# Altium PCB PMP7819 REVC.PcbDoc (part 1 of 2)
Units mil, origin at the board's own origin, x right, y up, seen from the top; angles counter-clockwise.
Board outline 2280 x 1450 mil, 4 copper layers (Top Layer, Mid-Layer 1, Mid-Layer 2, Bottom Layer), stack 62.2 mil thick; 94 components, 42 nets, 265 pads, 199 vias.
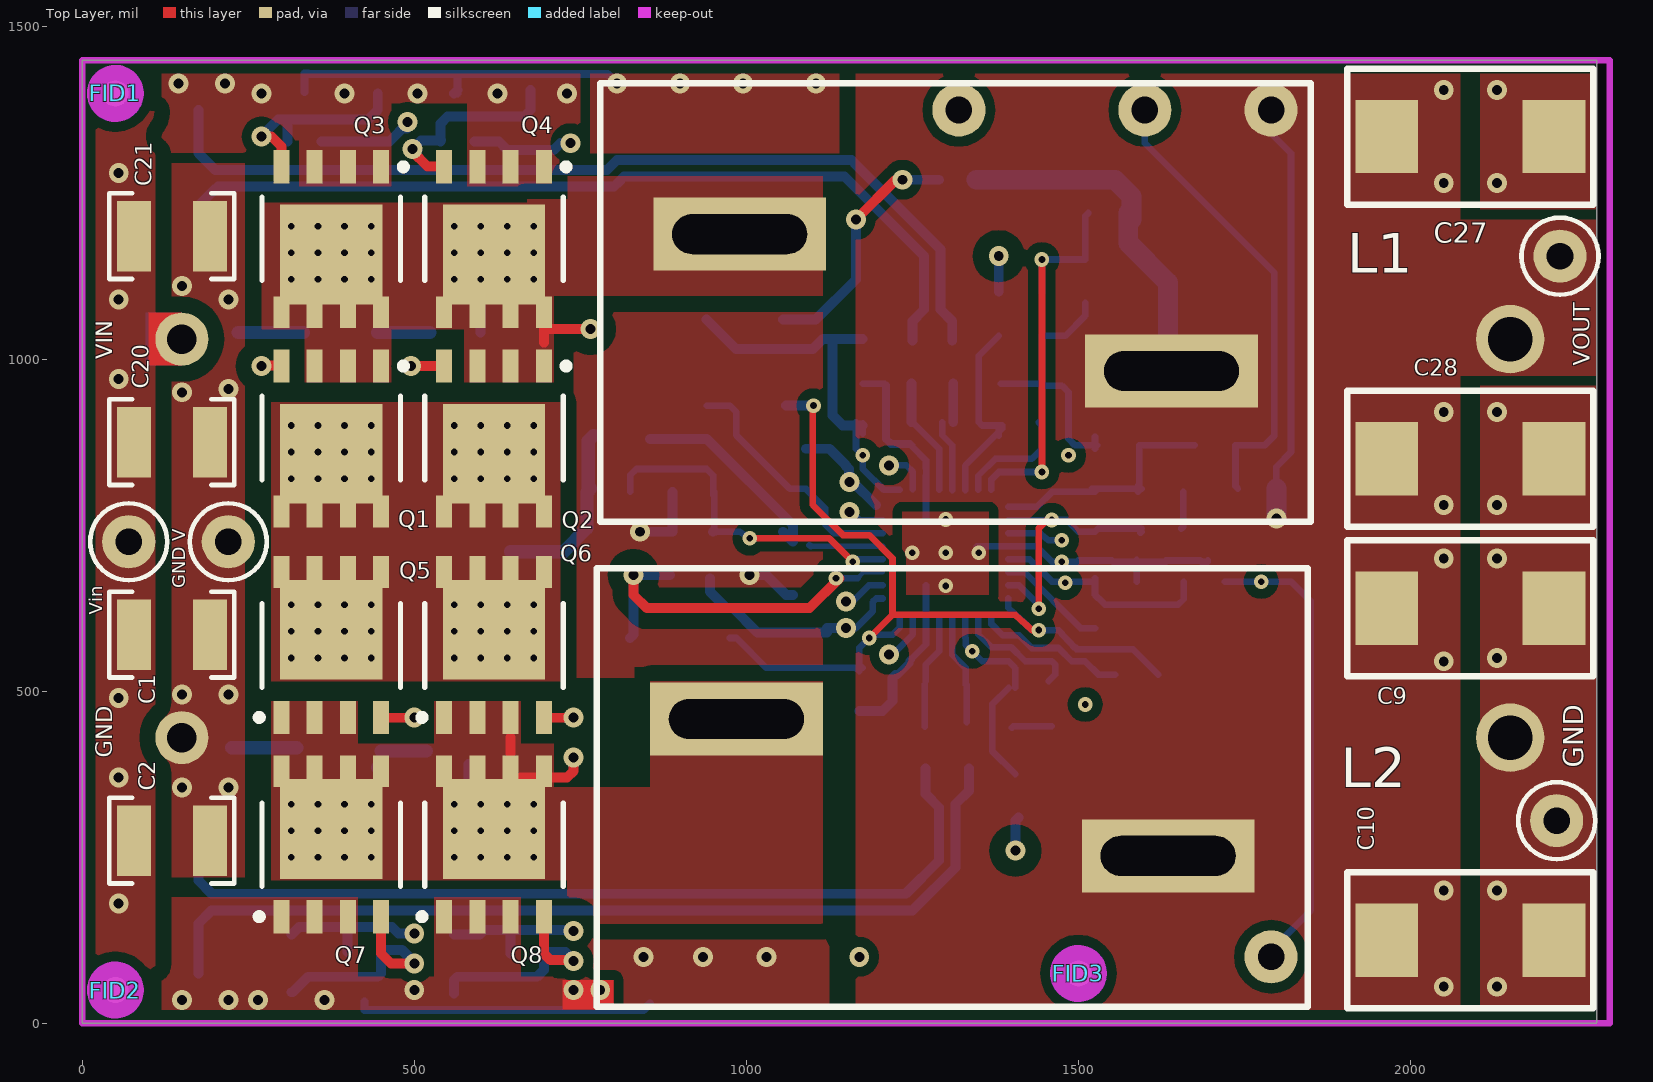
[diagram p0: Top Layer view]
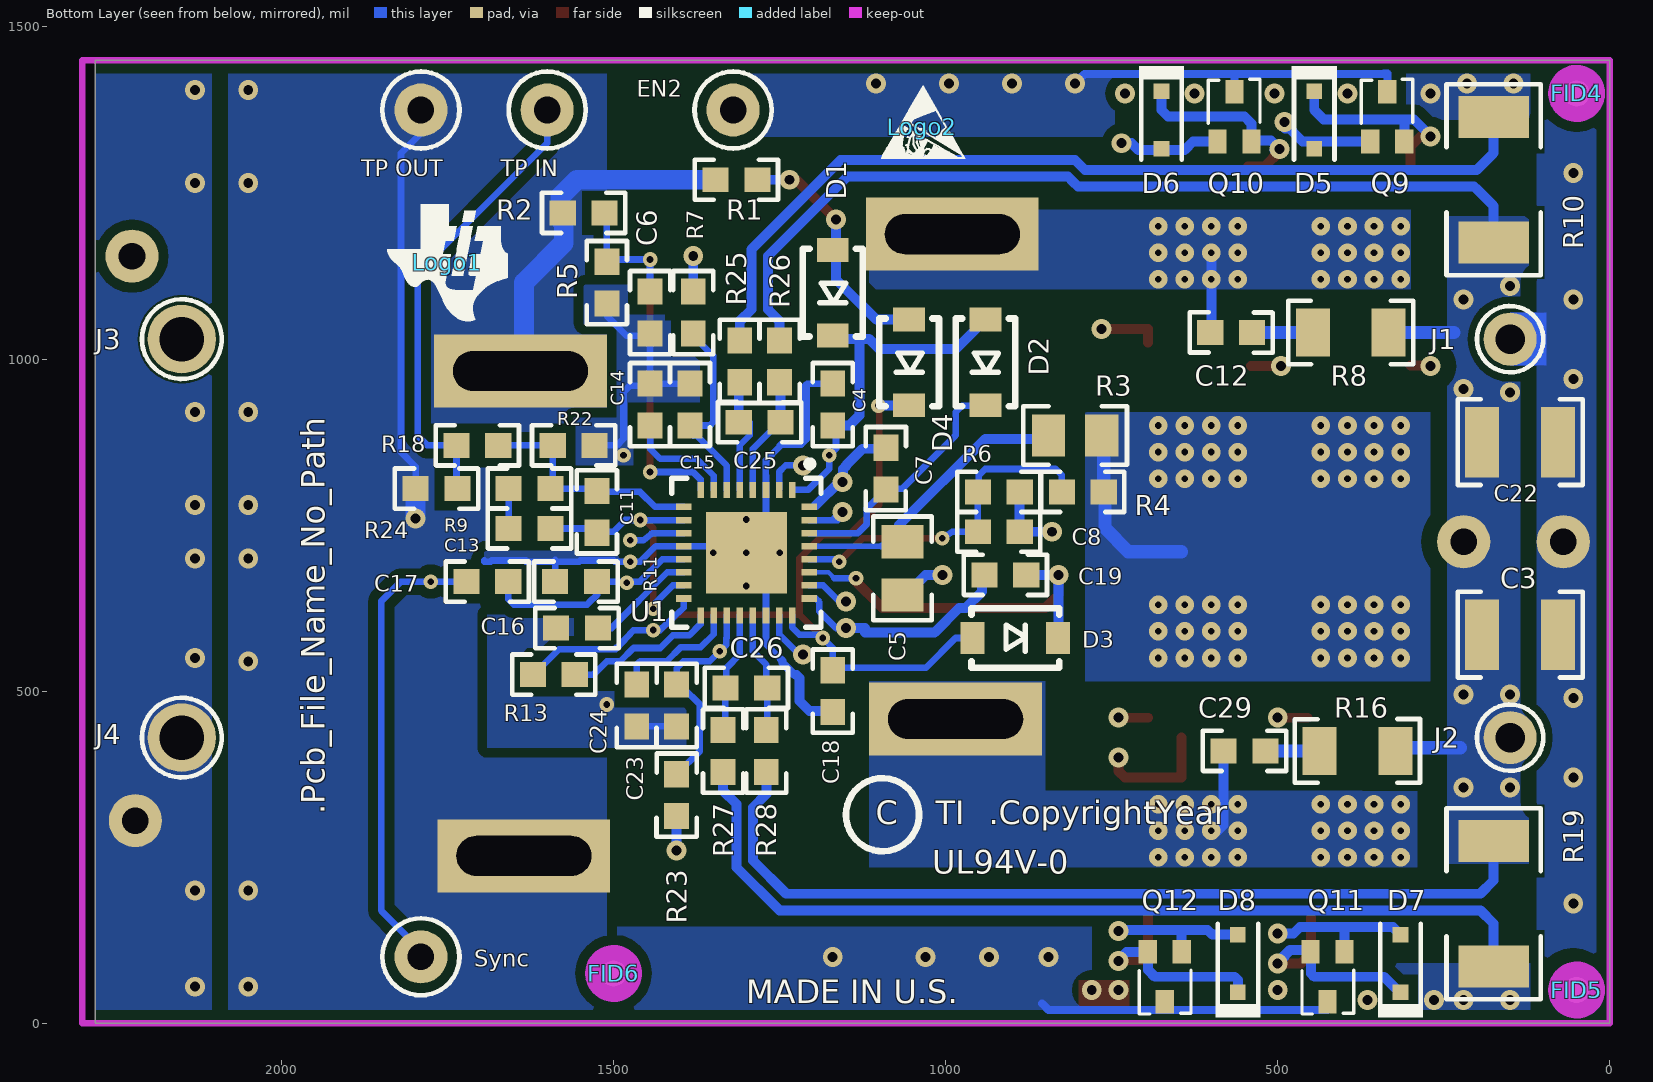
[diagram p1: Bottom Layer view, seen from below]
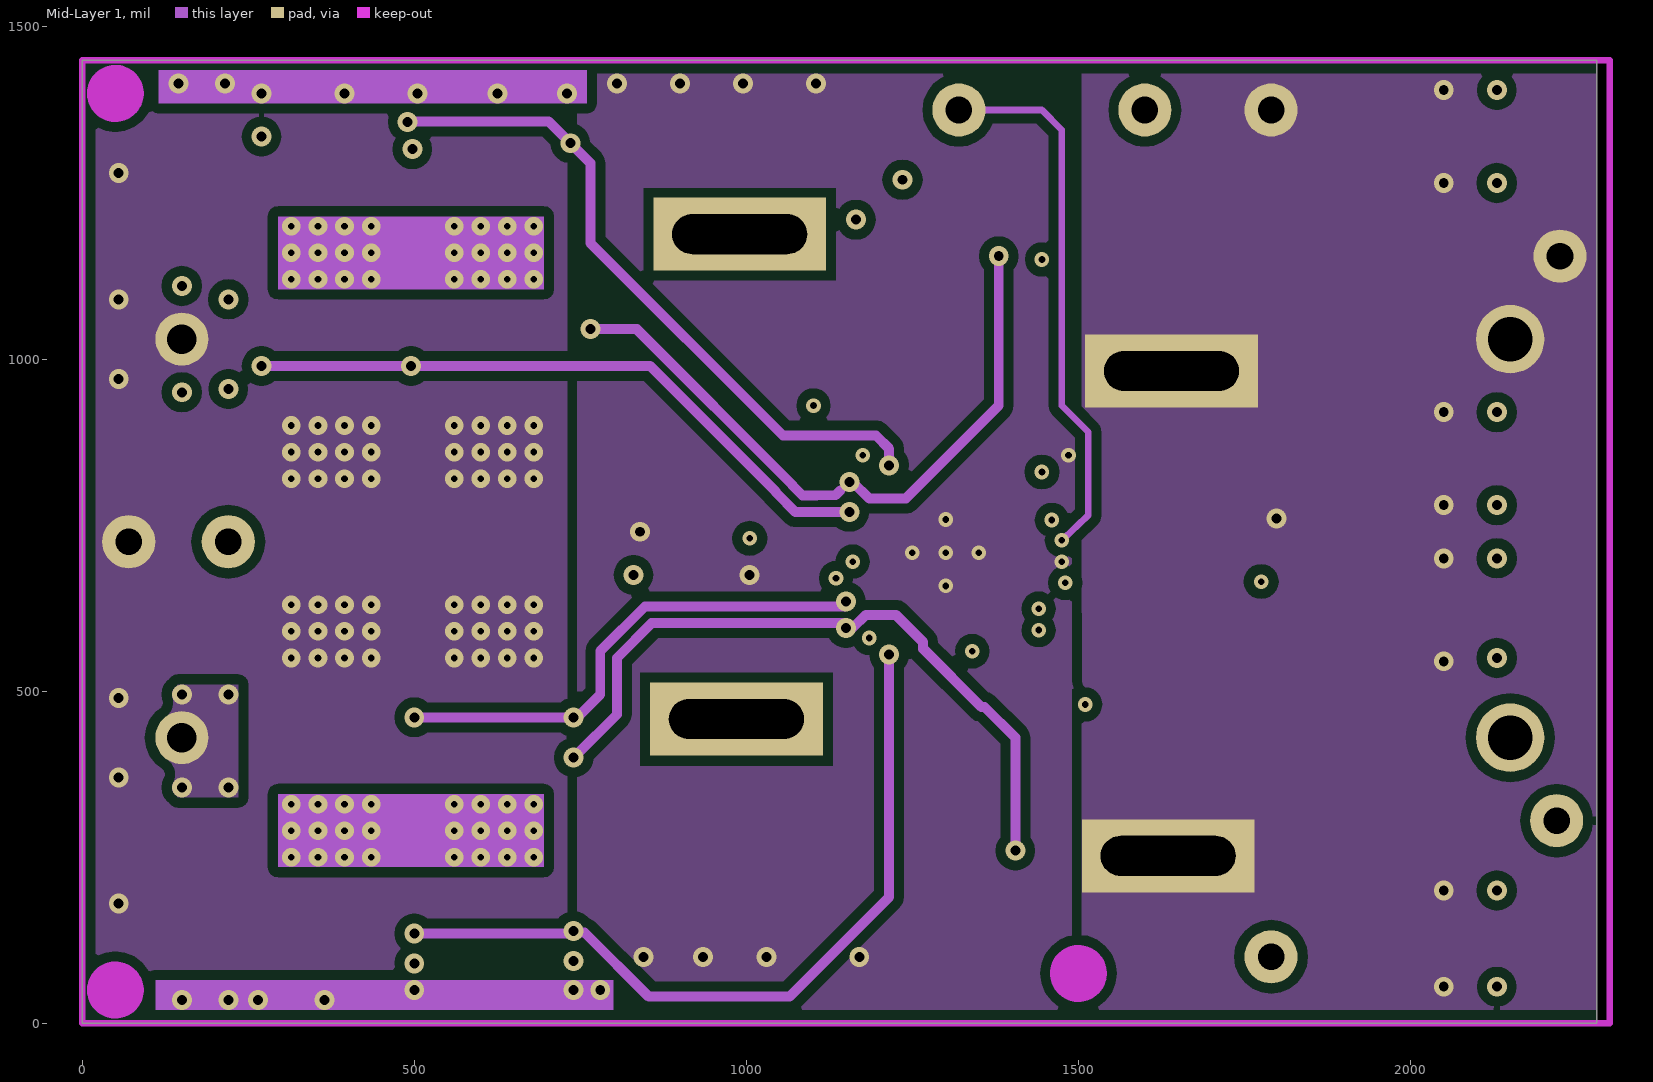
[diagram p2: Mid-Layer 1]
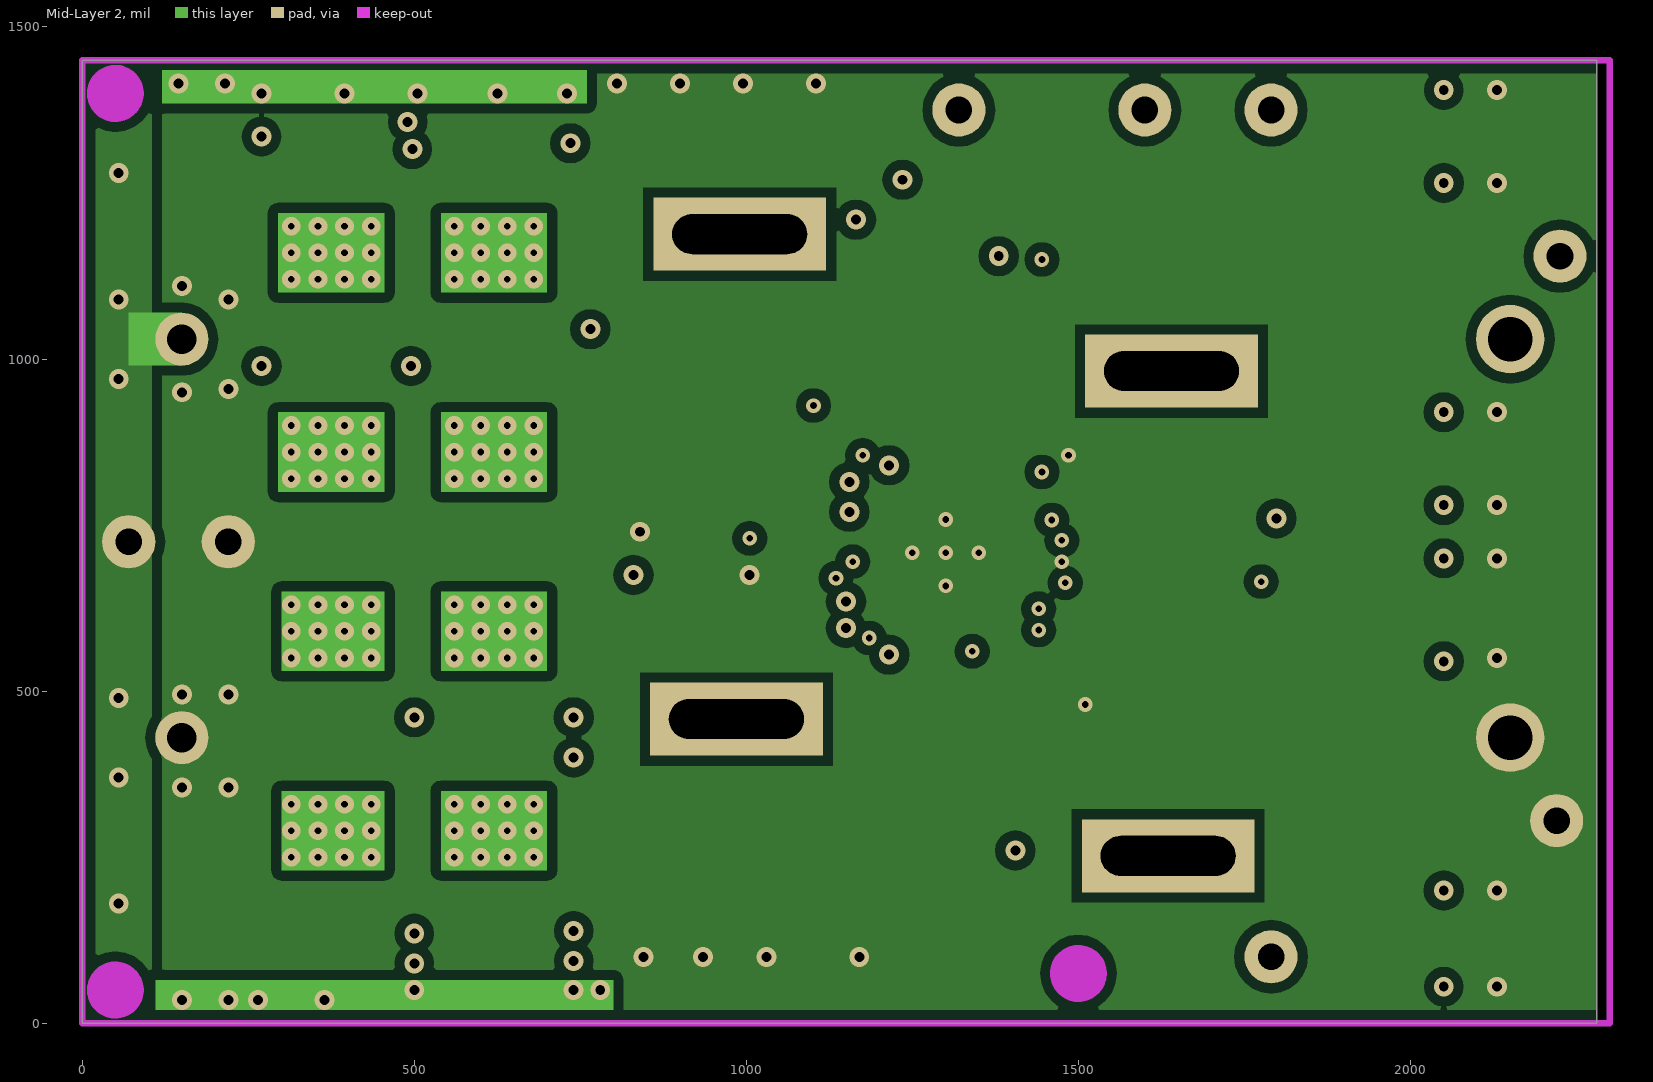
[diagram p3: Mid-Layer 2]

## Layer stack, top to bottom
Top Solder: solder mask 0.4, Solder Resist, Dk 3.5
Top Layer: signal copper 4.2
Dielectric1: core 10, FR-4, Dk 4.8
Mid-Layer 1: signal copper 1.4
Dielectric2: prepreg 31, FR-4, Dk 4.8
Mid-Layer 2: signal copper 1.4
Dielectric3: core 10, FR-4, Dk 4.8
Bottom Layer: signal copper 4.2
Bottom Solder: solder mask 0.4, Solder Resist, Dk 3.5

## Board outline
0,0 0,1450 2280,1450 2280,0

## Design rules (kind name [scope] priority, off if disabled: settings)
Clearance Clearance_Mid1_Polygon [(IsRegion AND OnLayer('Mid-Layer 1'))] p1: gap=15
Clearance Clearance_Mid2_Polygon [(IsRegion AND OnLayer('Mid-Layer 2'))] p2: gap=15
Clearance "Clearance_48V to 12V Exception" [(InNet('VIN') OR InNet('HO1_N') OR InNet('HO1_P') OR InNet('HO2_N') OR InNet('HO1_P') OR InNet('HB2')) vs (InNet('UVLO') OR InNet('VCC1') OR InNet('VCC2'))] p3: gap=8
Clearance "Clearance_48V to 12V" [InNetClass('48V') vs InNetClass('12V')] p4: gap=24
Clearance "Clearance_CS2_N TO H02_N" [InNet('CS2_N') vs InNet('HO2_N')] p5: gap=24
Clearance "Clearance_CS1_N TO H01_N" [InNet('CS1_N') vs InNet('HO1_N')] p6: gap=24
Clearance Clearance_Polygon [(IsRegion)] p7: gap=15
Clearance Clearance_ALL [All] p8: gap=8
ComponentClearance ComponentClearance_SmallPassives [HasFootprint('0201*') or HasFootprint('0402*') or HasFootprint('0508') or HasFootprint('0603*') or HasFootprint('0612') or HasFootprint('0805*') or HasFootprint('0815*') or HasFootprint('0830*') or HasFootprint('1206*') or HasFootprint('1210*') or HasFootprint('1808*') or HasFootprint('1812*') or HasFootprint('1825*') or HasFootprint('2010*') or HasFootprint('2220*') or HasFootprint('2225*') or HasFootprint('2512*') or HasFootprint('2728*') or HasFootprint('3518*') vs HasFootprint('0201*') or HasFootprint('0402*') or HasFootprint('0508') or HasFootprint('0603*') or HasFootprint('0612') or HasFootprint('0805*') or HasFootprint('0815*') or HasFootprint('0830*') or HasFootprint('1206*') or HasFootprint('1210*') or HasFootprint('1808*') or HasFootprint('1812*') or HasFootprint('1825*') or HasFootprint('2010*') or HasFootprint('2220*') or HasFootprint('2225*') or HasFootprint('2512*') or HasFootprint('2728*') or HasFootprint('3518*')] p1: gap=20 collisioncheckmode=3 verticalgap=10 showdistances=FALSE
ComponentClearance ComponentClearance_MountingHoles [(HasFootprint('NY PMS 440 0025 PH')) vs (HasFootprint('Keystone_1902C'))] p2: gap=5 collisioncheckmode=3 verticalgap=10 showdistances=FALSE
ComponentClearance [All] p3: gap=40 collisioncheckmode=3 verticalgap=10 showdistances=FALSE
DiffPairsRouting [All] p1: maxlimit=100 minlimit=10 mostfreqgap=10 toplayer_minwidth=15 toplayer_maxwidth=15 toplayer_prefwidth=15 midlayer1_minwidth=15 midlayer1_maxwidth=15 midlayer1_prefwidth=15 midlayer2_minwidth=15 midlayer2_maxwidth=15 midlayer2_prefwidth=15 bottomlayer_minwidth=15 bottomlayer_maxwidth=15 bottomlayer_prefwidth=15 maxuncoupledlength=1000
FabricationTestPointUsage TestPointUsage [All] p1: valid=0 allowmultiple=FALSE
FabricationTestpoint Testpoint [All] p1: side=3 testpointundercomponent=TRUE minsize=40 maxsize=100 preferedsize=60 minholesize=0 maxholesize=40 preferedholesize=32 testpointgrid=1 allowsidetop=TRUE allowsidebottom=TRUE usegrid=TRUE gridtolerance=0.01
FanoutControl Fanout_LCC [IsLCC] p1: bgadir=Out bgaviamode=Centered fanoutstyle=Auto fanoutdirection=Alternating viagrid=1 // Fanout_LCC (Default Rule)
FanoutControl Fanout_BGA [IsBGA] p2: bgadir=Out bgaviamode=Centered fanoutstyle=Auto fanoutdirection=Alternating viagrid=1 // Fanout_BGA (Default Rule)
FanoutControl Fanout_Default [All] p4: bgadir=Out bgaviamode=Centered fanoutstyle=Auto fanoutdirection=Alternating viagrid=1 // Fanout_Default (Default Rule)
FanoutControl Fanout_Small [(CompPinCount < 5)] p5: bgadir=Out bgaviamode=Centered fanoutstyle=Auto fanoutdirection=OutThenIn viagrid=1 // Fanout_Small (Default Rule)
HoleSize [All] p1: absolutevalues=TRUE maxlimit=251 minlimit=10 maxpercent=80.000 minpercent=20.000
MinimumAnnularRing [All] p1: minimumring=6
MinimumSolderMaskSliver [All] p1: minsoldermaskwidth=4
PlaneConnect [All] p1: planeconnectstyle=Direct reliefexpansion=10 reliefentries=4 reliefconductorwidth=10 reliefairgap=10
PolygonConnect [All] p1: connectstyle=Direct reliefconductorwidth=10 reliefentries=4 polygonreliefangle="90 Angle" airgapwidth=10
RoomDefinition "PMP7819 REV11" [InComponentClass('PMP7819 REV11')] p1: confinementstyle=ConfineIn formatcopy=TRUE lockcomponents=FALSE outline -2557,-5848 -557,-5848 -557,-4848 -2557,-4848
RoomDefinition Hardware_ANSI-B [InComponentClass('Hardware_ANSI-B')] p2: confinementstyle=ConfineIn formatcopy=TRUE lockcomponents=FALSE outline -2557,-5848 -557,-5848 -557,-4848 -2557,-4848
RoutingLayers [All] p1: top layer_v5=TRUE mid layer 1_v5=FALSE mid layer 2_v5=FALSE bottom layer_v5=TRUE
RoutingVias [All] p1: holewidth=28 width=50 viastyle="Through Hole" minholewidth=10 minwidth=20 maxholewidth=28 maxwidth=50
SilkToSilkClearance [All] p1: silktosilkclearance=5
SilkToSolderMaskClearance SilkscreenOverComponentPads [IsPad] p1: minsilkscreentomaskgap=5 clearancetoexposedcopper=TRUE
SolderMaskExpansion [All] p1: expansion=3
Width Width_CS1_N [InNet('CS1_N')] p1: maxlimit=15 minlimit=15 preferedwidth=15
Width Width_CS1_P [InNet('CS1_P')] p2: maxlimit=15 minlimit=15 preferedwidth=15
Width Width_CS2_N [InNet('CS2_N')] p3: maxlimit=15 minlimit=15 preferedwidth=15
Width Width_CS2_P [InNet('CS2_P')] p4: maxlimit=15 minlimit=15 preferedwidth=15
Width Width_LO1 [InNet('LO1')] p5: maxlimit=15 minlimit=15 preferedwidth=15
Width Width_LO2 [InNet('LO2')] p6: maxlimit=15 minlimit=15 preferedwidth=15
Width Width_HO1_P [InNet('HO1_P')] p7: maxlimit=30 minlimit=15 preferedwidth=15
Width Width_H01_N [InNet('HO1_N')] p8: maxlimit=30 minlimit=15 preferedwidth=15
Width Width_HO2_P [InNet('HO2_P')] p9: maxlimit=30 minlimit=15 preferedwidth=15
Width Width_HO2_N [InNet('HO2_N')] p10: maxlimit=30 minlimit=15 preferedwidth=15
Width Width_ALL [All] p11: maxlimit=100 minlimit=6 preferedwidth=10
16 further rules are at their usual default settings.

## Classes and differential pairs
net class 48V: HB1 HB2 HO1_N HO1_P HO2_N HO2_P VIN
net class 12V: COMP1 CS1 CS1_P CS2 CS2_P DEMB EN2 FB1 GND LO1 LO2 NetC12_1 NetC13_1 NetC29_1 NetD1_2 NetR18_2 RAMP1 RAMP2 RES RT SS1 SS2 SYNC UVLO VCC1 VCC2 VCCDIS VOUT1
differential pair HO2: +HO2_P -HO2_N
differential pair HO1: +HO1_P -HO1_N

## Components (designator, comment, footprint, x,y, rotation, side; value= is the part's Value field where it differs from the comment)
C1 "HMK325B7225KN-T" 1210 135,585 r0 top
C2 "HMK325B7225KN-T" 1210 135,275 r0 top
C3 "HMK325B7225KN-T" 1210 135,585 r0 bottom
C4 "GRM188R71C105KA12D" 0603 1170,931.5 r90 bottom
C5 "C2012X7R2A104K" 0805_HV 1065,685 r270 bottom
C6 "C1608X7R1H104K" 0603 1445,1070 r270 bottom
C7 "GRM188R72A104KA35D" 0603 1090,835 r270 bottom
C8 "06035A101JAT2A" 0603 920,740 r180 bottom
C9 "EEF-CD1B220R" "CD SP-CAP" 2090,625 r0 top locked
C10 "EEF-CD1B220R" "CD SP-CAP" 2090,125 r0 top locked
C11 "06035A101JAT2A" 0603 1525,770 r270 bottom
C12 "06031C272JAT2A" 0603 570,1040 r180 bottom
C13 "C1608X7R1H473K" 0603 1626.5,745 r180 bottom
C14 "C1608X7R1H104K" 0603 1445,931.5 r90 bottom
C15 "C0603C222K5RACTU" 0603 1385,931.5 r90 bottom
C16 "C1608X7R1H104K" 0603 1555,595 r0 bottom
C17 "06035A101JAT2A" 0603 1690,665 r180 bottom
C18 "GRM188R71C105KA12D" 0603 1170,500 r270 bottom
C19 "GRM188R72A104KA35D" 0603 910,675 r0 bottom
C20 "HMK325B7225KN-T" 1210 135,875 r0 top
C21 "HMK325B7225KN-T" 1210 135,1185 r0 top
C22 "HMK325B7225KN-T" 1210 135,875 r0 bottom
C23 "C0603C222K5RACTU" 0603 1405,478.5 r270 bottom
C24 "C1608X7R1H104K" 0603 1465,478.5 r270 bottom
C25 "GRM1885C1H101JA01D" 0603 1280,905 r0 bottom
C26 "GRM1885C1H101JA01D" 0603 1300,505 r180 bottom
C27 "EEF-CD1B220R" "CD SP-CAP" 2090,1335 r0 top locked
C28 "EEF-CD1B220R" "CD SP-CAP" 2090,850 r0 top locked
C29 "06031C272JAT2A" 0603 550,410 r180 bottom
D1 "BAT46W-7-F" SOD-123 1170,1100 r90 bottom
D2 "BAT46W-7-F" SOD-123 940,995 r90 bottom
D3 "BAT46W-7-F" SOD-123 895,580 r0 bottom
D4 "BAT46W-7-F" SOD-123 1055,995 r90 bottom
D5 "BAT54WS-7-F" sod-323 445,1360 r270 bottom
D6 "BAT54WS-7-F" sod-323 675,1360 r270 bottom
D7 "BAT54WS-7-F" sod-323 315,90 r90 bottom
D8 "BAT54WS-7-F" sod-323 560,90 r90 bottom
EN2 "5000" Keystone5000 1320,1375 r0 bottom
FID1 "Fiducial" Fiducial10-20 50,1400 r180 top
FID2 "Fiducial" Fiducial10-20 50,50 r180 top
FID3 "Fiducial" Fiducial10-20 1500,75 r90 top
FID4 "Fiducial" Fiducial10-20 50,1400 r0 bottom
FID5 "Fiducial" Fiducial10-20 50,50 r0 bottom
FID6 "Fiducial" Fiducial10-20 1500,75 r270 bottom
GND "5001" Keystone5001 2220,305 r0 top
"GND V" "5001" Keystone5001 220,725 r180 top
J1 "3102-2-00-21-00-00-08-0" 3102-2-00-21-00-00-08-0 150,1030 r180 bottom locked
J2 "3102-2-00-21-00-00-08-0" 3102-2-00-21-00-00-08-0 150,430 r180 bottom locked
J3 "3144-2-00-21-00-00-08-0" 3144-2-00-21-00-00-08-0 2150,1030 r180 bottom locked
J4 "3144-2-00-21-00-00-08-0" 3144-2-00-21-00-00-08-0 2150,430 r180 bottom locked
L1 "VER2923-103KL" VER2923 1315,1085 r0 top locked
L2 "VER2923-103KL" VER2923 1310,355 r0 top locked
Logo1 "Texas Instruments" TI_Symbol_Overlay_Small 1750,1145 r180 bottom
Logo2 "ESD Susceptible" ESD_Overlay_Small 1035,1350 r180 bottom
Q1 "BSC123N08NS3 G" PowerPAK_SO-8 375,880 r270 top locked
Q2 "BSC123N08NS3 G" PowerPAK_SO-8 620,880 r270 top locked
Q3 "BSC047N08NS3 G" PowerPAK_SO-8 375,1180 r270 top locked
Q4 "BSC047N08NS3 G" PowerPAK_SO-8 620,1180 r270 top locked
Q5 "BSC123N08NS3 G" PowerPAK_SO-8 375,570 r90 top locked
Q6 "BSC123N08NS3 G" PowerPAK_SO-8 620,570 r90 top locked
Q7 "BSC047N08NS3 G" PowerPAK_SO-8 375,270 r90 top locked
Q8 "BSC047N08NS3 G" PowerPAK_SO-8 620,270 r90 top locked
Q9 "2DB1694-7" "SOT-323 DIODES INC" 335,1365 r180 bottom
Q10 "2DB1694-7" "SOT-323 DIODES INC" 565,1365 r180 bottom
Q11 "2DB1694-7" "SOT-323 DIODES INC" 425,70 r0 bottom
Q12 "2DB1694-7" "SOT-323 DIODES INC" 670,70 r0 bottom
R1 "CRCW06030000Z0EA" 0603 1315,1270 r180 bottom
R2 "CRCW060310K0FKEA" 0603 1545,1220 r0 bottom
R3 "CRCW08051R00FNEA" 0805_HV 805,885 r180 bottom
R4 "CRCW0603133KFKEA" 0603 793.5,800 r180 bottom
R5 "CRCW06032K49FKEA" 0603 1510,1115 r270 bottom
R6 "CRCW060310K0FKEA" 0603 920,800 r0 bottom
R7 "CRCW060373K2FKEA" 0603 1380,1070 r90 bottom
R8 "CRCW12061R00FNEA" 1206 390,1040 r180 bottom
R9 "CRCW06033K32FKEA" 0603 1626.5,805 r180 bottom
R10 "WSL20103L000FEA" 2010M 175,1270 r90 bottom
R11 "CRCW060349K9FKEA" 0603 1556.5,665 r180 bottom
R13 "CRCW06030000Z0EA" 0603 1590,525 r180 bottom
R16 "CRCW12061R00FNEA" 1206 380,410 r180 bottom
R18 "CRCW060369K8FKEA" 0603 1705,870 r0 bottom
R19 "WSL20103L000FEA" 2010M 175,180 r270 bottom
R22 "CRCW06034K99FKEA" 0603 1560,870 r0 bottom
R23 "CRCW060373K2FKEA" 0603 1405,343.5 r270 bottom
R24 "CRCW060349R9FKEA" 0603 1766.5,805 r0 bottom
R25 "CRCW0603100RFKEA" 0603 1310,996.5 r90 bottom
R26 "CRCW0603100RFKEA" 0603 1250,996.5 r90 bottom
R27 "CRCW0603100RFKEA" 0603 1335,410 r90 bottom
R28 "CRCW0603100RFKEA" 0603 1270,410 r90 bottom
Sync "5000" Keystone5000 1790,100 r0 bottom
"TP IN" "5000" Keystone5000 1600,1375 r0 bottom
"TP OUT" "5000" Keystone5000 1790,1375 r0 bottom
U1 "LM5119" SQA32A 1300,708.44 r270 bottom locked
Vin "5000" Keystone5000 70,725 r0 top (schematic designator VIN)
VOUT "5000" Keystone5000 2225,1155 r0 top

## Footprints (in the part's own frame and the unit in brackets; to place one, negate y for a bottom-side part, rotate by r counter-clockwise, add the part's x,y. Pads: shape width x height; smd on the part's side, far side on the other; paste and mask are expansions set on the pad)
0603 [mm] "0603 from SM-752 data"
  rect 1x0.95 smd: 1(-0.8,0) 2(0.8,0)
  silkscreen extent -1.59,-0.77 1.59,0.77, body extent -0.87,-0.47 0.87,0.47, height 0.85
0805_HV [mil] "0805 with 30mil clearance between pads"
  rect 50x63 smd: 1(-40,0) 2(40,0)
  silkscreen extent -78,-44 78,44, body extent -43,-29 43,29, height 43
1206 [mm] "1206 from SM-752 data"
  rect 1.3x1.85 smd: 1(-1.45,0) 2(1.45,0)
  silkscreen extent -2.39,-1.22 2.39,1.22, body extent -1.7,-0.9 1.7,0.9, height 1.35
1210 [mm] "1210 from SM-752 data"
  rect 1.3x2.7 smd: 1(-1.45,0) 2(1.45,0)
  silkscreen extent -2.39,-1.64 2.39,1.64, body extent -1.7,-1.35 1.7,1.35, height 1.35
2010M [mm]
  rect 1.6x2.7 smd: 1(-2.4,0) 2(2.4,0)
  silkscreen extent -3.65,-1.8 3.65,1.8, body extent -2.73,-1.45 2.73,1.45, height 1.66
3102-2-00-21-00-00-08-0 [mil] "Mill-Max Connector Pin  40mil Diameter"
  round 80 hole 44: 1(0,0)
  silkscreen extent -50,-50 50,50, body extent -40,-40 40,40, height 100
3144-2-00-21-00-00-08-0 [mil] "Mill-Max Pin  67 Mill Drill"
  round 103 hole 67: 1(0,0)
  silkscreen extent -60,-60 60,60, body extent -50,-50 50,50, height 100
"CD SP-CAP" [mm] "PANASONIC SP-CAP CD SERIES"
  rect 2.4x2.8 smd: 1(-3.2,0) 2(3.2,0) 3(3.2,0)
  silkscreen extent -4.7,-2.6 4.7,2.6, body extent -4.72,-2.5 4.72,2.55, height 3.5
ESD_Overlay_Small [mil]
  silkscreen extent -62,-48 64,61
Fiducial10-20 [mm]
  round 1 smd paste-0.5 mask+0.5: 1(0,0)
  Keep-Out Layer circle w1.178: c0,0 r0.5
Keystone5000 [mil] "For Keystone 500x miniature loop terminals"
  round 80 hole 40: 1(0,0)
  silkscreen extent -58,-58 58,58, body extent -49,-49 49,49, height 182
Keystone5001 [mil] "For Keystone 500x miniature loop terminals"
  round 80 hole 40: 1(0,0)
  silkscreen extent -58,-58 58,58, body extent -49,-49 49,49, height 182
PowerPAK_SO-8 [mil] "Vishay PowerPAK SO-8, Body 5.3x6.0mm (max), Pitch 1.27mm, IPC Medium Density"
  rect 50x24 smd mask+2.99: 1(-109.5,75) 2(-109.5,25) 3(-109.5,-25) 4(-109.5,-75)
  rect 48x24 smd mask+2.99: 5(109.5,-75) 8(109.5,75)
  rect 48x24 smd paste-12 mask+2.99: 6(109.5,-25) 7(109.5,25)
  rect 150x154 smd paste-75 mask+2.99: 9(22.5,0)
  silkscreen extent -114,-104 62,113, body extent -121,-102 121,102, height 43
SOD-123 [mm] "On Semi recommended land pattern"
  rect 0.915x1.22 smd: 1(-1.637,0) 2(1.637,0)
  silkscreen extent -1.68,-1.14 1.68,1.14, body extent -1.42,-0.9 1.42,0.9, height 1.35
sod-323 [mm] "NXP recommended land pattern"
  rect 0.6x0.6 smd paste-0.05: 1(-1.1,0) 2(1.1,0)
  silkscreen extent -2.06,-0.86 1.53,0.86, body extent -1.3,-0.67 1.3,0.68, height 1.1
"SOT-323 DIODES INC" [mm] "STO-323 DIODES INC"
  round 0.25 on Bottom Overlay: 0(-1.3,-0.95)
  rect 0.7x0.9 smd: 1(-0.65,-0.95) 2(0.65,-0.95) 3(0,0.95)
  silkscreen extent -1,-0.25 0.97,1.43, body extent -1,-1.45 0.97,1.5, height 1
SQA32A [mm] "QFN, 32-Leads, Body 5x5mm, Pitch 0.5mm, NSC Recommended"
  rect 0.6x0.25 smd paste-0.125 mask+0.051: 1(-2.4,1.75) 2(-2.4,1.25) 3(-2.4,0.75) 4(-2.4,0.25) 5(-2.4,-0.25) 6(-2.4,-0.75) 7(-2.4,-1.25) 8(-2.4,-1.75) 17(2.4,-1.75) 18(2.4,-1.25) 19(2.4,-0.75) 20(2.4,-0.25) 21(2.4,0.25) 22(2.4,0.75) 23(2.4,1.25) 24(2.4,1.75)
  rect 0.25x0.6 smd paste-0.125 mask+0.051: 9(-1.75,-2.4) 10(-1.25,-2.4) 11(-0.75,-2.4) 12(-0.25,-2.4) 13(0.25,-2.4) 14(0.75,-2.4) 15(1.25,-2.4) 16(1.75,-2.4) 25(1.75,2.4) 26(1.25,2.4) 27(0.75,2.4) 28(0.25,2.4) 29(-0.25,2.4) 30(-0.75,2.4) 31(-1.25,2.4) 32(-1.75,2.4)
  rect 3.1x3.1 smd paste-1.55 mask+0.051: 33(0,0)
  silkscreen extent -3.52,-2.85 2.85,2.85, body extent -2.55,-2.55 2.55,2.55, height 0.8
TI_Symbol_Overlay_Small [mil]
  silkscreen extent -90,-88 91,88
VER2923 [mil] "COILCRAFT VER2923"
  rect 260x110 hole 60 slot 203 at 0 deg: 1(-325,103) 2(325,-103)
  silkscreen extent -535,-330 535,330, body extent -535,-330 535,330, height 875

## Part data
C1 C2 C3 C20 C21 C22: "CAP, CERM, 2.2uF, 100V, +/-10%, X7R, 1210"
C4 C18: "CAP, CERM, 1uF, 16V, +/-10%, X7R, 0603"
C5: "CAP, CERM, 0.1uF, 100V, +/-10%, X7R, 0805"
C6 C14 C16 C24: "CAP, CERM, 0.1uF, 50V, +/-10%, X7R, 0603"
C7 C19: "CAP, CERM, 0.1uF, 100V, +/-10%, X7R, 0603"
C8 C11 C17 C25 C26: "CAP, CERM, 100pF, 50V, +/-5%, C0G/NP0, 0603"
C9 C10 C27 C28: "CAP ALUM 22UF 12.5V 20% SMD"
C12 C29: "CAP, CERM, 2700pF, 100V, +/-5%, X7R, 0603"
C13: "CAP, CERM, 0.047uF, 50V, +/-10%, X7R, 0603"
C15 C23: "CAP, CERM, 2200pF, 50V, +/-10%, X7R, 0603"
D1 D2 D3 D4: "Diode, Schottky, 100V, 0.15A, SOD-123"
D5 D6 D7 D8: "Diode, Schottky, 30V, 0.2A, SOD-323"
EN2 Sync "TP IN" "TP OUT" Vin VOUT: "Test Point, TH, Miniature, Red"
FID1 FID2 FID3 FID4 FID5 FID6: "Fiducial mark.  There is nothing to buy or mount."
GND "GND V": "Test Point, TH, Miniature, Black"
J1 J2: "PC PIN .040 DIA 3102-2 SERIES"
J3 J4: "CIRCUIT PIN PRNTD .188\" .084\""
L1 L2: "Inductor, Shielded E Core, Ferrite, 10.0uH, 34A, .0023 ohm, SMD"
Logo1: library part TI_Logo, "Texas Instrument Corporate Signature"
Logo2: library part ESD_Susceptible, "ESD Susceptible Symbol"
Q1 Q2 Q5 Q6: "MOSFET, N-CH, 80V, 55A, PG-TDSON-8"
Q3 Q4 Q7 Q8: "MOSFET, N-CH, 80V, 100A, PG-TDSON-8"
Q9 Q10 Q11 Q12: "TRANS BIPO PNP 30V 1A SOT-323"
R1 R13: "RES, 0 ohm, 5%, 0.1W, 0603"
R2 R6: "RES, 10.0k ohm, 1%, 0.1W, 0603"
R3: "RES, 1.00 ohm, 1%, 0.125W, 0805"
R4: "RES, 133k ohm, 1%, 0.1W, 0603"
R5: "RES, 2.49k ohm, 1%, 0.1W, 0603"
R7 R23: "RES, 73.2k ohm, 1%, 0.1W, 0603"
R8 R16: "RES, 1.00 ohm, 1%, 0.25W, 1206"
R9: "RES, 3.32k ohm, 1%, 0.1W, 0603"
R10 R19: "RES, 0.003 ohm, 1%, 0.5W, 2010"
R11: "RES, 49.9k ohm, 1%, 0.1W, 0603"
R18: "RES, 69.8k ohm, 1%, 0.1W, 0603"
R22: "RES, 4.99k ohm, 1%, 0.1W, 0603"
R24: "RES, 49.9 ohm, 1%, 0.1W, 0603"
R25 R26 R27 R28: "RES, 100 ohm, 1%, 0.1W, 0603"
U1: library part LM5119PSQE/NOPB, "IC CTRL SYNC BUCK DUAL 32-LLP"

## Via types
v1: diameter 28, hole 10, Top Layer to Bottom Layer, tented top, 96 vias
v2: diameter 30, hole 15, Top Layer to Bottom Layer, 80 vias
v3: diameter 22, hole 10, Top Layer to Bottom Layer, 23 vias

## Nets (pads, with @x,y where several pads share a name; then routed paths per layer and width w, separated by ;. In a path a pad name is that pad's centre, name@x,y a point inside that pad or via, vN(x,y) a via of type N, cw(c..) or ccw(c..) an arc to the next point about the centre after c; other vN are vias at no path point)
COMP1: C11.2 C13.2 U1.10 U1.15 | length 416.9
  Top Layer w10: v3@1440,625 1440,745 v3@1455,760
  Bottom Layer w9.84: U1.15@1394.49,659.23 1410.77,659.23 1440,630 v3@1440,625 ; U1.10@1394.49,757.65 1452.35,757.65 v3@1455,755
  Bottom Layer w10: v3@1455,757.65 1482.35,757.65 1500,740 1525,740 1530,745 C13.2@1595,745 ; C13.2@1593.5,738.5 C13.2@1595,740
  other v3: 1440,624 1460,757.65
CS1: C25.2 R25.1 U1.5 | length 166.9
  Bottom Layer w10: C25.2@1295,905 1295,885.34 1310,870.34 1310,850.31 1309.84,850.16 U1.5@1309.84,802.93
  Bottom Layer w15: C25.2@1311.5,905 R25.1@1311.5,963.5
CS1_P: Q3.1 Q3.2 Q3.3 Q4.1 Q4.2 Q4.3 R10.2 R25.2 | length 1399.5
  Bottom Layer w15: R10.2@175,1375 R10.2@175,1364.49 175,1310 200.32,1284.68 790.32,1284.68 805.39,1299.75 1158.11,1299.75 1165.43,1292.43 1292.5,1165.36 1292.5,1074.5 1310,1057 R25.2@1310,1027.99
  other v2: 270,1400 395,1400 505,1400 625,1400 730,1400 145,1415 215,1415
CS2: C26.1 R27.2 U1.20 | length 168.8
  Bottom Layer w9.84: U1.20@1309.84,613.95 1309.84,555.16 1330,535 C26.1@1330,510 ; R27.2@1331.5,453.5 C26.1@1331.5,510
CS2_P: Q7.1 Q7.2 Q7.3 Q8.1 Q8.2 Q8.3 R19.2 R27.1 | length 1407.2
  Bottom Layer w15: R19.2@175,75 R19.2@175,85.51 175,150 195,170 1250.36,170 1315,234.64 1315,330 1335,350 R27.1@1335,378.5 R27.1@1335,383.5
  other v2: 150,35 220,35 265,35 365,35 500,50 740,50 780,50
CSG1: C25.1 R26.1 U1.4 | length 170.1
  Bottom Layer w9.84: C25.1@1255,900 1290.16,864.84 U1.4@1290.16,802.93
  Bottom Layer w15: C25.1@1248.5,905 R26.1@1248.5,963.5
CSG2: C26.2 R28.2 U1.21 | length 170.8
  Bottom Layer w10: R28.2@1268.5,446.5 C26.2@1268.5,510 ; C26.2@1270,515 1270,540 1290.16,560.16 U1.21@1290.16,613.95
DEMB: R13.2 U1.17 | length 230.5
  Bottom Layer w9.84: U1.17@1368.9,613.95 1368.9,601.1 1385.76,584.24 1410.53,584.24 1429.77,565 1469.77,565 1489.77,545 1510,545 1530,525 R13.2@1555,525
EN2: EN2.1 U1.11 | length 903.7
  Mid-Layer 1 w9.84: EN2.1@1320,1375 1445,1375 1475,1345 1475,930 1515,890 1515,765 v3(1475,727)
  Bottom Layer w9.84: U1.11@1394.49,737.97 1442.03,737.97 1443.87,736.13 1444.11,736.13 1455.23,727 v3(1475,727)
FB1: C11.1 R9.2 R18.1 R22.2 U1.9 | length 364.1
  Bottom Layer w9.84: U1.9@1394.49,777.34 1437.34,777.34 1460,800 C11.1@1525,800 ; R9.2@1588.5,801.5 R9.2@1590,800
  Bottom Layer w10: C11.1@1520,805 R9.2@1595,805 ; R9.2@1590,810 1591.5,808.5 R22.2@1591.5,870 R18.1@1675,870
GND: "GND V.1" C1.2 C2.2 C3.2 C4.2 C5.2 C6.2 C8.2 C9.2 C9.3 C10.2 C10.3 C14.2 C15.2 C16.2 C18.2 C20.2 C21.2 C22.2 C23.2 C24.2 C27.2 C27.3 C28.2 C28.3 GND.1 J2.1 J4.1 Q9.3 Q10.3 Q11.3 Q12.3 R5.2 R6.1 R8.2 R10.1 R11.1 R16.2 R19.1 R22.1 R26.2 R28.1 U1.3 U1.12 U1.22 U1.33 | length 5467.4
  Bottom Layer w9.84: C4.2@1175,962.99 1208.01,962.99 ; 1247.92,547.92 1270.47,570.47 U1.22@1270.47,613.95 U1.33@1270.47,659.53 ; 1250,870 1250,867.94 1270.47,847.47 1270.47,835.72 1270.67,835.72 1270.67,824.47 1270.47,824.28 U1.3@1270.47,802.93 1270.47,760.47 U1.33@1270,760 ; U1.33@1346.72,718.28 U1.12@1394.49,718.28 1436.72,718.28 1460,695
  Bottom Layer w10: C15.2@1382.99,962.99 C14.2@1440,962.99 ; C23.2@1400,445 1402.01,447.01 C24.2@1460,447.01 ; C14.2@1445,960 1475,960 1485,950 1485,880 1495,870 R22.1@1528.5,870 ; C14.2@1445,962.99 1445,1035 1480,1035 1510,1065 R5.2@1510,1085 ; 1460,695 1498.23,695 1499.93,696.7 1550.07,696.7 1551.77,695 1631.73,695 1631.73,696.7 1683.57,696.7 1685.27,695 1694.73,695 1694.73,696.7 ; R22.1@1525,865 R22.1@1525,882.99 ; R11.1@1587.99,665 1587.99,697.99
  Bottom Layer w12: Q9.3@335,1402.4 335,1430 340,1430 ; 339.12,1429.12 565,1429.12 ; Q11.3@425,32.6 425,20 845,20 855,30 ; Q10.3@565,1400 Q10.3@565,1402.4 565,1405 565,1429.12 ; v2(805,1415) 790.88,1429.12 565,1429.12 ; 1210,960 1210,880 1218,872 1223,872 ; 1224.5,524.5 1227.63,524.5 1245.5,542.37 1245.5,545.5 1247.92,547.92 ; 1226,872 1246,872
  Bottom Layer w15: R19.1@175,290 R19.1@175,274.49 175,215 195,195 1240,195 1290,245 1290,325 1270,345 R28.1@1270,378.5 R28.1@1270,383.5 ; R10.1@175,1175 R10.1@175,1175.51 175,1230.71 201.97,1257.68 ; 203,1258 204.68,1259.68 800.68,1259.68 808,1267 815.75,1274.75 1147.75,1274.75 1267.5,1155 1267.5,1074.5 1250,1057 R26.2@1250,1027.99 ; Q10.3@560,1400 Q10.3@565,1405 ; v2@835,740 C8.2@888.5,740 ; C8.2@888.5,741.5 R6.1@888.5,800 ; v2@1010,675 1030,675 1060,645 C5.2@1070,645 ; C18.2@1170,470 1205,470 1220,485 1220,520 1224.5,524.5
  Bottom Layer w20: 225,415 R16.2@322.91,415 ; 235,1040 R8.2@332.91,1040
  other v2: 2130,55 845,100 935,100 1030,100 1170,100 2130,200 150,355 220,355 150,495 220,495 2130,550 1005,675 2130,700 840,740 2130,780 2130,920 150,950 220,955 220,1090 150,1110 2130,1265 2130,1405 900,1415 995,1415 1105,1415
  other v3: 1510,480 1300,658.44 1475,695 1250,708.44 1300,708.44 1350,708.44 1300,758.44 1485,855
HB1: C7.2 D2.1 U1.30 | length 378.7
  Bottom Layer w9.84: D2.1@940,930 975,930 985,920 985,885 1065,805 C7.2@1090,805 ; C7.2@1090,803.5 1118.5,775 1118.5,751.5 1132.03,737.97 U1.30@1205.51,737.97
HB2: C19.1 D3.1 U1.27 | length 588.2
  Top Layer w15: v2(830,675) 830,645 850,625 1095,625 v3@1140,670
  Bottom Layer w7: 1167.42,670 1176.33,678.91 U1.27@1205.51,678.91
  Bottom Layer w9.84: v3@1140,670 1167.42,670
  Bottom Layer w15: D3.1@825,580 830,585 v2(830,675) C19.1@885,675
  other v3: 1135,670
HO1_N: C7.1 C12.1 L1.1 Q1.1 Q1.2 Q1.3 Q2.1 Q2.2 Q2.3 Q3.5 Q3.6 Q3.7 Q3.8 Q3.9 Q4.5 Q4.6 Q4.7 Q4.8 Q4.9 R7.2 U1.32 | length 1418
  Top Layer w15: 695,1025 695,1045 v2(765,1045)
  Mid-Layer 1 w15: v2(765,1045) 835,1045 1069.5,810.5 1069.5,809.44 1084.44,794.5 1105.56,794.5 1106.06,795 1134.04,795 1141.54,802.5 ; v2(1155,815) 1160,815 1185,790 1240,790 1380,930 v2(1380,1155)
  Bottom Layer w15: C12.1@600,1040 v1(600,1160) ; C7.1@1090,865 1125,865 1149.5,840.5 1149.5,839.44 1154.58,834.36 1154.58,826.54 1155,826.12 v2(1155,815) 1160.07,815 U1.32@1195,780.07 ; R7.2@1380,1101.5 v2(1380,1155)
  other v1: 315,1120 355,1120 395,1120 435,1120 560,1120 600,1120 640,1120 680,1120 315,1160 355,1160 395,1160 435,1160 560,1160 640,1160 680,1160 315,1200 355,1200 395,1200 435,1200 560,1200 600,1200 640,1200 680,1200
HO1_P: Q1.4 Q2.4 U1.31 | length 1094.8
  Top Layer w15: v2@270,990 Q1.4@300,990 ; v2(495,989.5) Q2.4@540,989.5
  Mid-Layer 1 w15: v2(270,989.5) v2@490.5,989.5 ; v2(495,989.5) 855,989.5 ; 854.82,989.82 1044.5,800.14 1044.5,799.08 1074.08,769.5 1115.92,769.5 1116.42,770 v2@1145,770
  Bottom Layer w9.84: v2@1162.65,757.65 U1.31@1205.51,757.65
  Bottom Layer w15: v2(1155,770) v2@1165,760
HO2_N: C19.2 C29.1 L2.1 Q5.1 Q5.2 Q5.3 Q6.1 Q6.2 Q6.3 Q7.5 Q7.6 Q7.7 Q7.8 Q7.9 Q8.5 Q8.6 Q8.7 Q8.8 Q8.9 R23.2 U1.25 | length 1752.6
  Top Layer w15: 645,430 645,370 730,370 740,380 v2(740,400)
  Mid-Layer 1 w15: v2@742,402 744,400 744,404 805,465 805,550 857.5,602.5 1147.5,602.5 v2@1155,595 ; v2(1150,595) 1160,595 1180,615 1225,615 1266.25,573.75 1266.25,563.75 1353.75,476.25 1358.75,476.25 1405,430 v2(1405,260)
  Bottom Layer w9.84: v2@1155,595 1165,595 1190,620 1190,634.09 1195.46,639.54 U1.25@1205.51,639.54
  Bottom Layer w15: 581.5,390 581.5,298.5 590,290 v1(600,290) ; C19.2@945,670 945,650 970,625 980,625 1016.5,588.5 1121.05,588.5 1121.05,595 v2@1155,595 ; v2(1405,260) 1405,305 R23.2@1410,310
  other v1: 315,250 355,250 395,250 435,250 560,250 600,250 640,250 680,250 315,290 355,290 395,290 435,290 560,290 640,290 680,290 315,330 355,330 395,330 435,330 560,330 600,330 640,330 680,330
HO2_P: Q5.4 Q6.4 U1.26 | length 913.6
  Top Layer w15: Q5.4@455,460 v2@500,460 ; Q6.4@695,460 v2@740,460
  Mid-Layer 1 w15: v2(500,460.5) v2(740,460.5) ; v2@745.5,460.5 780,495 780,560.36 847.14,627.5 1147.5,627.5 1155,635 v2@1155,637.5
  Bottom Layer w9.84: v2@1160,635 1184.23,659.23 U1.26@1205.51,659.23
  Bottom Layer w15: v2(740,460.5) v2@745.5,460.5
  other v2: 1150,635
LO1: D5.2 D6.2 Q9.1 Q10.1 U1.2 | length 1405.3
  Mid-Layer 1 w15: v2@490,1350 498,1358 702,1358 v2(735,1325) 765,1295 765,1175 1055,885 1195,885 1215,865 v2@1215,845 ; v2@1215,850 v2@1220,845
  Bottom Layer w9.84: v2@1215,845 1220,840 1240.79,840 1250.79,830 U1.2@1250.79,803.72
  Bottom Layer w15: Q9.1@360.59,1327.6 462.6,1327.6 490,1355 490,1348.13 489.37,1347.5 v2@484.5,1347.5 ; Q10.1@590.59,1327.6 627.4,1327.6 640,1315 710,1315 720,1325 v2(735,1325)
  other v2: 1215,840 490,1357
LO2: D7.2 D8.2 Q11.1 Q12.1 U1.23 | length 1712.9
  Mid-Layer 1 w15: v2(500,135) v2@740,135 ; v2@740.5,136.5 756.5,136.5 853,40 1065,40 1215,190 v2(1215,555)
  Bottom Layer w9.84: v2@1215,550 1250.79,585.79 U1.23@1250.79,613.95
  Bottom Layer w15: D7.2@315,133.31 326.69,145 466.41,145 476.41,135 v2(500,135) ; Q11.1@399.41,107.4 399.41,145 ; D8.2@560,133.31 598.31,133.31 605.62,140.62 645,140.62 ; Q12.1@645,105 645,140.62 ; v2@740,135 734.38,140.62 645,140.62
  other v2: 740,139
NetC12_2: C12.2 R8.1 | length 78.5
  Bottom Layer w20: R8.1@445,1040 C12.2@523.5,1040
NetC13_1: C13.1 R9.1 | length 56.2
  Bottom Layer w10: C13.1@1655,745 1657.99,747.99 R9.1@1657.99,800
NetC29_2: C29.2 R16.1 | length 75.6
  Bottom Layer w20: R16.1@445,385 R16.1@450,390 ; R16.1@450,410 C29.2@518.5,410
NetD1_2: D1.2 D4.2 R1.2 | length 377
  Top Layer w15: v2@1165,1205 v2@1170,1205 ; v2(1165,1210) 1225,1270 v2(1235,1270)
  Bottom Layer w15: D4.2@1055,1059.47 1104.47,1059.47 1165,1120 1165,1200 v2@1170,1205 ; v2(1235,1270) R1.2@1290,1270
NetD5_1: D5.1 Q3.4 Q9.2 | length 319.6
  Top Layer w15: v2(270,1335) 285,1335 300,1320 Q3.4@300,1289.5 Q3.4@300,1285
  Bottom Layer w15: v2@265,1335 269.18,1335 295,1360.81 430.82,1360.81 445,1375 D5.1@445,1400 ; Q9.2@309.41,1327.6 309.41,1354.41
NetD6_1: D6.1 Q4.4 Q10.2 | length 317.3
  Top Layer w15: v2(497,1316) 497,1313 520,1290 Q4.4@545,1290
  Bottom Layer w15: v2(497,1316) 510,1329 539,1329 Q10.2@539.41,1329.41 ; v2@500,1310 v2@505,1315 ; Q10.2@539.41,1327.6 Q10.2@539.41,1329.41 ; Q10.2@540,1330 Q10.2@539.41,1329.41 ; D6.1@675,1405 D6.1@675,1403.31 675,1375 665,1365 550,1365 539.41,1354.41 Q10.2@539.41,1329.41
